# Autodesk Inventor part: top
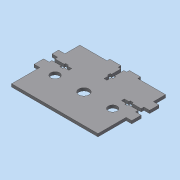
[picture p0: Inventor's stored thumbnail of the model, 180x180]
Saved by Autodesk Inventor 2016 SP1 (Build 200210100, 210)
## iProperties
Created: 2016-06
Part Number: top
Material: Generic
Document SubType Name: Modeling
Designer: Mohamed A.
Density: 1 g/cm^3
Appearance: Default
Author: Mohamed A.
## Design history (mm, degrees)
sketch "Sketch1"
  geometry: L1 (46, 2.505)-(52, 2.505) reference; L2 (52, -7.495)-(52, 2.505) reference; L3 (46, -7.495)-(52, -7.495) reference; L4 (46, -7.495)-(46, -37.5) reference; L5 (46, -37.5)-(-46, -37.5) reference; L6 (-46, -37.5)-(-46, -7.495) reference; L7 (-46, -7.495)-(-52, -7.495) reference; L8 (-52, 2.505)-(-52, -7.495) reference; L9 (-46, 2.505)-(-52, 2.505) reference; L10 (-46, 2.505)-(-46, 5.455) reference; L11 (-46, 5.455)-(-36, 5.455) reference; L12 (-36, 5.455)-(-36, 4.005) reference; L13 (-36, 4.005)-(-33, 4.005) reference; L14 (-33, 4.005)-(-33, 5.455) reference; L15 (-33, 5.455)-(-28, 5.455) reference; L16 (-28, 5.455)-(-28, 8.555) reference; L17 (-28, 8.555)-(-33, 8.555) reference; L18 (-33, 8.555)-(-33, 10.005) reference; L19 (-33, 10.005)-(-36, 10.005) reference; L20 (-36, 10.005)-(-36, 8.555) reference; L21 (-36, 8.555)-(-46, 8.555) reference; L22 (-46, 8.555)-(-46, 11.505) reference; L23 (-46, 11.505)-(-52, 11.505) reference; L24 (-52, 18.555)-(-52, 11.505) reference; L25 (-52, 18.555)-(-45.295, 18.555) reference; L26 (-45.295, 18.555)-(-45.295, 34.5) reference; L27 (-45.295, 34.5)-(-16.333, 34.5) reference; L28 (-16.333, 34.5)-(-16.333, 37.5) reference; L29 (-16.333, 37.5)-(-4.5, 37.5) reference; L30 (-4.5, 37.5)-(-4.5, 34.5) reference; L31 (-4.5, 34.5)-(-1.55, 34.5) reference; L32 (-1.55, 34.5)-(-1.55, 24.5) reference; L33 (-1.55, 24.5)-(-3, 24.5) reference; L34 (-3, 24.5)-(-3, 21.5) reference; L35 (-3, 21.5)-(-1.55, 21.5) reference; L36 (-1.55, 21.5)-(-1.55, 16.5) reference; L37 (-1.55, 16.5)-(1.55, 16.5) reference; L38 (1.55, 16.5)-(1.55, 21.5) reference; L39 (1.55, 21.5)-(3, 21.5) reference; L40 (3, 21.5)-(3, 24.5) reference; L41 (3, 24.5)-(1.55, 24.5) reference; L42 (1.55, 24.5)-(1.55, 34.5) reference; L43 (1.55, 34.5)-(4.5, 34.5) reference; L44 (4.5, 34.5)-(4.5, 37.5) reference; L45 (4.5, 37.5)-(16.333, 37.5) reference; L46 (16.333, 37.5)-(16.333, 34.5) reference; L47 (16.333, 34.5)-(46, 34.5) reference; L48 (46, 34.5)-(46, 21.505) reference; L49 (46, 21.505)-(52, 21.505) reference; L50 (52, 11.505)-(52, 21.505) reference; L51 (46, 11.505)-(52, 11.505) reference; L52 (46, 11.505)-(46, 8.555) reference; L53 (46, 8.555)-(36, 8.555) reference; L54 (36, 8.555)-(36, 10.005) reference; L55 (36, 10.005)-(33, 10.005) reference; L56 (33, 10.005)-(33, 8.555) reference; L57 (33, 8.555)-(28, 8.555) reference; L58 (28, 8.555)-(28, 5.455) reference; L59 (28, 5.455)-(33, 5.455) reference; L60 (33, 5.455)-(33, 4.005) reference; L61 (33, 4.005)-(36, 4.005) reference; L62 (36, 4.005)-(36, 5.455) reference; L63 (36, 5.455)-(46, 5.455) reference; L64 (46, 5.455)-(46, 2.505) reference; C1 r 4.7 at (30.7, -6.5) reference; C2 r 1.4 at (15.5, -22) reference; C3 r 1.4 at (-15.5, 9) reference; C4 r 1.4 at (15.5, 9) reference; C5 r 1.4 at (-15.5, -22) reference; C6 r 4.7 at (-30.7, -6.5) reference; C7 r 12.5 at (0, -6.5) reference
extrude "Extrusion1" new body sketch "Sketch1" distance "d2" = 3; taper "d3" = 0 deg
sketch "Sketch2"
  geometry: C1 r 4.7 at (30.7, -6.5) reference; C2 r 3.5 at (0, -6.5) reference; C3 r 4.7 at (-30.7, -6.5) reference; C4 r 5.5 at (0, -6.5); 1 further point
  constraints: 1 centre point
  dimensions: "d4" = 2 radial gap between concentric circles of C2 C4
extrude "Extrusion2" cut sketch "Sketch2" distance "d5" = 3; taper "d6" = 0 deg
sketch "Sketch3"
  geometry: 1 further point
body "Solid1"
node "Reference1"
node "Reference2"
node "Reference3"
node "Reference4"
